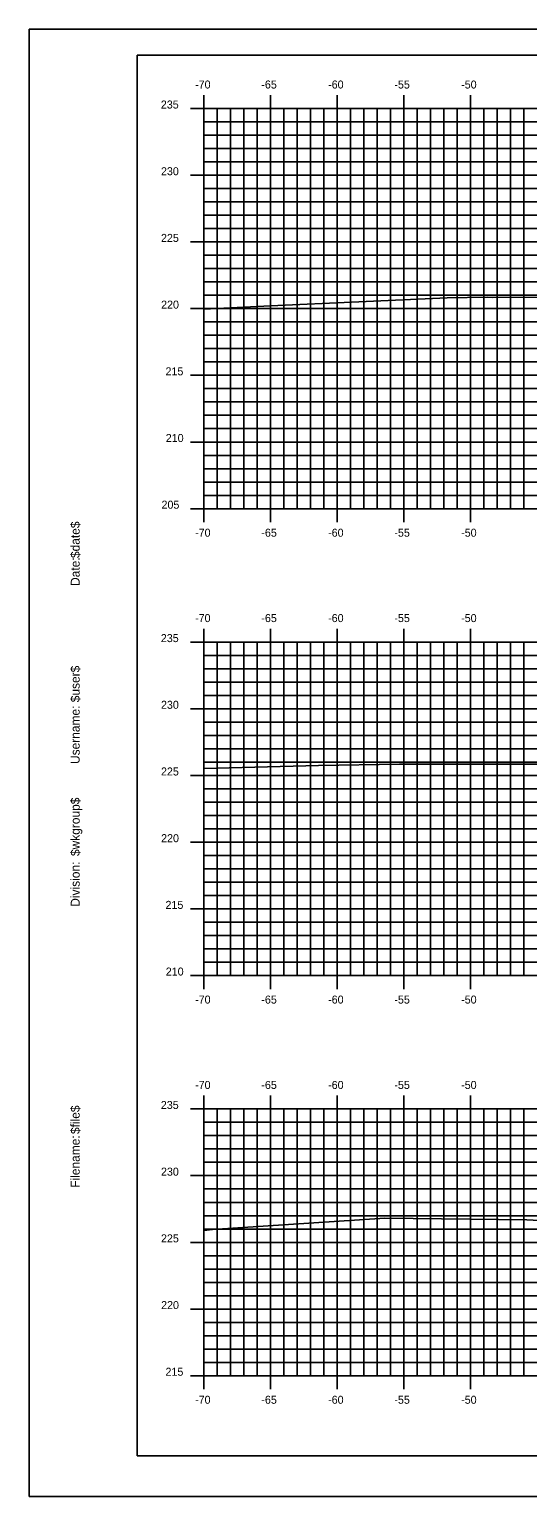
# Model space of a CAD drawing. Extents: x 1137876 to 1138046, y 608981 to 609091.
# Drawn here: x 1137876.1 to 1137913.5, y 608981.3 to 609091.3 of the extents above; entities that cross this region are included whole.
import ezdxf

# ---------------------------------------------------------------- set-up
doc = ezdxf.new("R2010")
doc.units = 0
for name, color, linetype in [('BORDER', 7, 'Continuous'), ('H_V ANNOTATION', 7, 'Continuous'), ('MAJOR', 7, 'Continuous'), ('MINOR', 7, 'Continuous'), ('PLOT BOUNDARY', 7, 'Continuous'), ('S_Roadway_Centerline', 7, 'Continuous')]:
    doc.layers.add(name, color=color, linetype=linetype)

msp = doc.modelspace()

# ---------------------------------------------------------------- linework, layer by layer
at = {"layer": 'BORDER'}
msp.add_lwpolyline([(1137884.17, 608984.34), (1138044.17, 608984.34), (1138044.17, 609089.34), (1137884.17, 609089.34)], close=True, dxfattribs=at)
at = {"layer": 'MAJOR'}
for p, q in [((1137889.17, 609086.34), (1137889.17, 609085.34)), ((1137894.17, 609086.34), (1137894.17, 609085.34)), ((1137899.17, 609086.34), (1137899.17, 609085.34)), ((1137904.17, 609086.34), (1137904.17, 609085.34)), ((1137909.17, 609086.34), (1137909.17, 609085.34)), ((1137888.16, 609085.34), (1137889.17, 609085.34)), ((1137889.17, 609085.34), (1138029.17, 609085.34)), ((1137889.17, 609055.34), (1137889.17, 609085.34)), ((1137889.17, 609055.34), (1137889.17, 609085.34)), ((1137889.17, 609085.34), (1138029.17, 609085.34)), ((1137894.17, 609055.34), (1137894.17, 609085.34)), ((1137899.17, 609055.34), (1137899.17, 609085.34)), ((1137904.17, 609055.34), (1137904.17, 609085.34)), ((1137909.17, 609055.34), (1137909.17, 609085.34)), ((1137888.16, 609080.34), (1137889.17, 609080.34)), ((1137889.17, 609080.34), (1138029.17, 609080.34)), ((1137888.16, 609075.34), (1137889.17, 609075.34)), ((1137889.17, 609075.34), (1138029.17, 609075.34)), ((1137888.16, 609070.34), (1137889.17, 609070.34)), ((1137889.17, 609070.34), (1138029.17, 609070.34)), ((1137888.16, 609065.34), (1137889.17, 609065.34)), ((1137889.17, 609065.34), (1138029.17, 609065.34)), ((1137888.16, 609060.34), (1137889.17, 609060.34)), ((1137889.17, 609060.34), (1138029.17, 609060.34)), ((1137888.16, 609055.34), (1137889.17, 609055.34)), ((1137889.17, 609055.34), (1138029.17, 609055.34)), ((1137889.17, 609055.34), (1138029.17, 609055.34)), ((1137889.17, 609054.33), (1137889.17, 609055.34)), ((1137894.17, 609054.33), (1137894.17, 609055.34)), ((1137899.17, 609054.33), (1137899.17, 609055.34)), ((1137904.17, 609054.33), (1137904.17, 609055.34)), ((1137909.17, 609054.33), (1137909.17, 609055.34)), ((1137889.17, 609046.34), (1137889.17, 609045.34)), ((1137894.17, 609046.34), (1137894.17, 609045.34)), ((1137899.17, 609046.34), (1137899.17, 609045.34)), ((1137904.17, 609046.34), (1137904.17, 609045.34)), ((1137909.17, 609046.34), (1137909.17, 609045.34)), ((1137888.16, 609045.34), (1137889.17, 609045.34)), ((1137889.17, 609045.34), (1138029.17, 609045.34)), ((1137889.17, 609020.34), (1137889.17, 609045.34)), ((1137889.17, 609020.34), (1137889.17, 609045.34)), ((1137889.17, 609045.34), (1138029.17, 609045.34)), ((1137894.17, 609020.34), (1137894.17, 609045.34)), ((1137899.17, 609020.34), (1137899.17, 609045.34)), ((1137904.17, 609020.34), (1137904.17, 609045.34)), ((1137909.17, 609020.34), (1137909.17, 609045.34)), ((1137888.16, 609040.34), (1137889.17, 609040.34)), ((1137889.17, 609040.34), (1138029.17, 609040.34)), ((1137888.16, 609035.34), (1137889.17, 609035.34)), ((1137889.17, 609035.34), (1138029.17, 609035.34)), ((1137888.16, 609030.34), (1137889.17, 609030.34)), ((1137889.17, 609030.34), (1138029.17, 609030.34)), ((1137888.16, 609025.34), (1137889.17, 609025.34)), ((1137889.17, 609025.34), (1138029.17, 609025.34)), ((1137888.16, 609020.34), (1137889.17, 609020.34)), ((1137889.17, 609020.34), (1138029.17, 609020.34)), ((1137889.17, 609020.34), (1138029.17, 609020.34)), ((1137889.17, 609019.33), (1137889.17, 609020.34)), ((1137894.17, 609019.33), (1137894.17, 609020.34)), ((1137899.17, 609019.33), (1137899.17, 609020.34)), ((1137904.17, 609019.33), (1137904.17, 609020.34)), ((1137909.17, 609019.33), (1137909.17, 609020.34)), ((1137889.17, 609011.34), (1137889.17, 609010.34)), ((1137894.17, 609011.34), (1137894.17, 609010.34)), ((1137899.17, 609011.34), (1137899.17, 609010.34)), ((1137904.17, 609011.34), (1137904.17, 609010.34)), ((1137909.17, 609011.34), (1137909.17, 609010.34)), ((1137888.16, 609010.34), (1137889.17, 609010.34)), ((1137889.17, 609010.34), (1138029.17, 609010.34)), ((1137889.17, 608990.34), (1137889.17, 609010.34)), ((1137889.17, 608990.34), (1137889.17, 609010.34)), ((1137889.17, 609010.34), (1138029.17, 609010.34)), ((1137894.17, 608990.34), (1137894.17, 609010.34)), ((1137899.17, 608990.34), (1137899.17, 609010.34)), ((1137904.17, 608990.34), (1137904.17, 609010.34)), ((1137909.17, 608990.34), (1137909.17, 609010.34)), ((1137888.16, 609005.34), (1137889.17, 609005.34)), ((1137889.17, 609005.34), (1138029.17, 609005.34)), ((1137888.16, 609000.34), (1137889.17, 609000.34)), ((1137889.17, 609000.34), (1138029.17, 609000.34)), ((1137888.16, 608995.34), (1137889.17, 608995.34)), ((1137889.17, 608995.34), (1138029.17, 608995.34)), ((1137888.16, 608990.34), (1137889.17, 608990.34)), ((1137889.17, 608990.34), (1138029.17, 608990.34)), ((1137889.17, 608990.34), (1138029.17, 608990.34)), ((1137889.17, 608989.33), (1137889.17, 608990.34)), ((1137894.17, 608989.33), (1137894.17, 608990.34)), ((1137899.17, 608989.33), (1137899.17, 608990.34)), ((1137904.17, 608989.33), (1137904.17, 608990.34)), ((1137909.17, 608989.33), (1137909.17, 608990.34))]:
    msp.add_line(p, q, dxfattribs=at)
at = {"layer": 'MINOR'}
for p, q in [((1137889.17, 609084.34), (1138029.17, 609084.34)), ((1137889.17, 609084.34), (1137890.17, 609084.34)), ((1137890.17, 609055.34), (1137890.17, 609085.34)), ((1137891.17, 609055.34), (1137891.17, 609085.34)), ((1137892.17, 609055.34), (1137892.17, 609085.34)), ((1137893.17, 609055.34), (1137893.17, 609085.34)), ((1137895.17, 609055.34), (1137895.17, 609085.34)), ((1137896.17, 609055.34), (1137896.17, 609085.34)), ((1137897.17, 609055.34), (1137897.17, 609085.34)), ((1137898.17, 609055.34), (1137898.17, 609085.34)), ((1137900.17, 609055.34), (1137900.17, 609085.34)), ((1137901.17, 609055.34), (1137901.17, 609085.34)), ((1137902.17, 609055.34), (1137902.17, 609085.34)), ((1137903.17, 609055.34), (1137903.17, 609085.34)), ((1137905.17, 609055.34), (1137905.17, 609085.34)), ((1137906.17, 609055.34), (1137906.17, 609085.34)), ((1137907.17, 609055.34), (1137907.17, 609085.34)), ((1137908.17, 609055.34), (1137908.17, 609085.34)), ((1137910.17, 609055.34), (1137910.17, 609085.34)), ((1137911.17, 609055.34), (1137911.17, 609085.34)), ((1137912.17, 609055.34), (1137912.17, 609085.34)), ((1137913.17, 609055.34), (1137913.17, 609085.34)), ((1137889.17, 609083.34), (1138029.17, 609083.34)), ((1137889.17, 609083.34), (1137890.17, 609083.34)), ((1137889.17, 609082.34), (1138029.17, 609082.34)), ((1137889.17, 609082.34), (1137890.17, 609082.34)), ((1137889.17, 609081.34), (1138029.17, 609081.34)), ((1137889.17, 609081.34), (1137890.17, 609081.34)), ((1137889.17, 609079.34), (1138029.17, 609079.34)), ((1137889.17, 609079.34), (1137890.17, 609079.34)), ((1137889.17, 609078.34), (1138029.17, 609078.34)), ((1137889.17, 609078.34), (1137890.17, 609078.34)), ((1137889.17, 609077.34), (1138029.17, 609077.34)), ((1137889.17, 609077.34), (1137890.17, 609077.34)), ((1137889.17, 609076.34), (1138029.17, 609076.34)), ((1137889.17, 609076.34), (1137890.17, 609076.34)), ((1137889.17, 609074.34), (1138029.17, 609074.34)), ((1137889.17, 609074.34), (1137890.17, 609074.34)), ((1137889.17, 609073.34), (1138029.17, 609073.34)), ((1137889.17, 609073.34), (1137890.17, 609073.34)), ((1137889.17, 609072.34), (1138029.17, 609072.34)), ((1137889.17, 609072.34), (1137890.17, 609072.34)), ((1137889.17, 609071.34), (1138029.17, 609071.34)), ((1137889.17, 609071.34), (1137890.17, 609071.34)), ((1137889.17, 609069.34), (1138029.17, 609069.34)), ((1137889.17, 609069.34), (1137890.17, 609069.34)), ((1137889.17, 609068.34), (1138029.17, 609068.34)), ((1137889.17, 609068.34), (1137890.17, 609068.34)), ((1137889.17, 609067.34), (1138029.17, 609067.34)), ((1137889.17, 609067.34), (1137890.17, 609067.34)), ((1137889.17, 609066.34), (1138029.17, 609066.34)), ((1137889.17, 609066.34), (1137890.17, 609066.34)), ((1137889.17, 609064.34), (1138029.17, 609064.34)), ((1137889.17, 609064.34), (1137890.17, 609064.34)), ((1137889.17, 609063.34), (1138029.17, 609063.34)), ((1137889.17, 609063.34), (1137890.17, 609063.34)), ((1137889.17, 609062.34), (1138029.17, 609062.34)), ((1137889.17, 609062.34), (1137890.17, 609062.34)), ((1137889.17, 609061.34), (1138029.17, 609061.34)), ((1137889.17, 609061.34), (1137890.17, 609061.34)), ((1137889.17, 609059.34), (1138029.17, 609059.34)), ((1137889.17, 609059.34), (1137890.17, 609059.34)), ((1137889.17, 609058.34), (1138029.17, 609058.34)), ((1137889.17, 609058.34), (1137890.17, 609058.34)), ((1137889.17, 609057.34), (1138029.17, 609057.34)), ((1137889.17, 609057.34), (1137890.17, 609057.34)), ((1137889.17, 609056.34), (1138029.17, 609056.34)), ((1137889.17, 609056.34), (1137890.17, 609056.34)), ((1137890.17, 609020.34), (1137890.17, 609045.34)), ((1137891.17, 609020.34), (1137891.17, 609045.34)), ((1137892.17, 609020.34), (1137892.17, 609045.34)), ((1137893.17, 609020.34), (1137893.17, 609045.34)), ((1137895.17, 609020.34), (1137895.17, 609045.34)), ((1137896.17, 609020.34), (1137896.17, 609045.34)), ((1137897.17, 609020.34), (1137897.17, 609045.34)), ((1137898.17, 609020.34), (1137898.17, 609045.34)), ((1137900.17, 609020.34), (1137900.17, 609045.34)), ((1137901.17, 609020.34), (1137901.17, 609045.34)), ((1137902.17, 609020.34), (1137902.17, 609045.34)), ((1137903.17, 609020.34), (1137903.17, 609045.34)), ((1137905.17, 609020.34), (1137905.17, 609045.34)), ((1137906.17, 609020.34), (1137906.17, 609045.34)), ((1137907.17, 609020.34), (1137907.17, 609045.34)), ((1137908.17, 609020.34), (1137908.17, 609045.34)), ((1137910.17, 609020.34), (1137910.17, 609045.34)), ((1137911.17, 609020.34), (1137911.17, 609045.34)), ((1137912.17, 609020.34), (1137912.17, 609045.34)), ((1137913.17, 609020.34), (1137913.17, 609045.34)), ((1137889.17, 609044.34), (1138029.17, 609044.34)), ((1137889.17, 609044.34), (1137890.17, 609044.34)), ((1137889.17, 609043.34), (1138029.17, 609043.34)), ((1137889.17, 609043.34), (1137890.17, 609043.34)), ((1137889.17, 609042.34), (1138029.17, 609042.34)), ((1137889.17, 609042.34), (1137890.17, 609042.34)), ((1137889.17, 609041.34), (1138029.17, 609041.34)), ((1137889.17, 609041.34), (1137890.17, 609041.34)), ((1137889.17, 609039.34), (1138029.17, 609039.34)), ((1137889.17, 609039.34), (1137890.17, 609039.34)), ((1137889.17, 609038.34), (1138029.17, 609038.34)), ((1137889.17, 609038.34), (1137890.17, 609038.34)), ((1137889.17, 609037.34), (1138029.17, 609037.34)), ((1137889.17, 609037.34), (1137890.17, 609037.34)), ((1137889.17, 609036.34), (1138029.17, 609036.34)), ((1137889.17, 609036.34), (1137890.17, 609036.34)), ((1137889.17, 609034.34), (1138029.17, 609034.34)), ((1137889.17, 609034.34), (1137890.17, 609034.34)), ((1137889.17, 609033.34), (1138029.17, 609033.34)), ((1137889.17, 609033.34), (1137890.17, 609033.34)), ((1137889.17, 609032.34), (1138029.17, 609032.34)), ((1137889.17, 609032.34), (1137890.17, 609032.34)), ((1137889.17, 609031.34), (1138029.17, 609031.34)), ((1137889.17, 609031.34), (1137890.17, 609031.34)), ((1137889.17, 609029.34), (1138029.17, 609029.34)), ((1137889.17, 609029.34), (1137890.17, 609029.34)), ((1137889.17, 609028.34), (1138029.17, 609028.34)), ((1137889.17, 609028.34), (1137890.17, 609028.34)), ((1137889.17, 609027.34), (1138029.17, 609027.34)), ((1137889.17, 609027.34), (1137890.17, 609027.34)), ((1137889.17, 609026.34), (1138029.17, 609026.34)), ((1137889.17, 609026.34), (1137890.17, 609026.34)), ((1137889.17, 609024.34), (1138029.17, 609024.34)), ((1137889.17, 609024.34), (1137890.17, 609024.34)), ((1137889.17, 609023.34), (1138029.17, 609023.34)), ((1137889.17, 609023.34), (1137890.17, 609023.34)), ((1137889.17, 609022.34), (1138029.17, 609022.34)), ((1137889.17, 609022.34), (1137890.17, 609022.34)), ((1137889.17, 609021.34), (1138029.17, 609021.34)), ((1137889.17, 609021.34), (1137890.17, 609021.34)), ((1137890.17, 608990.34), (1137890.17, 609010.34)), ((1137891.17, 608990.34), (1137891.17, 609010.34)), ((1137892.17, 608990.34), (1137892.17, 609010.34)), ((1137893.17, 608990.34), (1137893.17, 609010.34)), ((1137895.17, 608990.34), (1137895.17, 609010.34)), ((1137896.17, 608990.34), (1137896.17, 609010.34)), ((1137897.17, 608990.34), (1137897.17, 609010.34)), ((1137898.17, 608990.34), (1137898.17, 609010.34)), ((1137900.17, 608990.34), (1137900.17, 609010.34)), ((1137901.17, 608990.34), (1137901.17, 609010.34)), ((1137902.17, 608990.34), (1137902.17, 609010.34)), ((1137903.17, 608990.34), (1137903.17, 609010.34)), ((1137905.17, 608990.34), (1137905.17, 609010.34)), ((1137906.17, 608990.34), (1137906.17, 609010.34)), ((1137907.17, 608990.34), (1137907.17, 609010.34)), ((1137908.17, 608990.34), (1137908.17, 609010.34)), ((1137910.17, 608990.34), (1137910.17, 609010.34)), ((1137911.17, 608990.34), (1137911.17, 609010.34)), ((1137912.17, 608990.34), (1137912.17, 609010.34)), ((1137913.17, 608990.34), (1137913.17, 609010.34)), ((1137889.17, 609009.34), (1138029.17, 609009.34)), ((1137889.17, 609009.34), (1137890.17, 609009.34)), ((1137889.17, 609008.34), (1138029.17, 609008.34)), ((1137889.17, 609008.34), (1137890.17, 609008.34)), ((1137889.17, 609007.34), (1138029.17, 609007.34)), ((1137889.17, 609007.34), (1137890.17, 609007.34)), ((1137889.17, 609006.34), (1138029.17, 609006.34)), ((1137889.17, 609006.34), (1137890.17, 609006.34)), ((1137889.17, 609004.34), (1138029.17, 609004.34)), ((1137889.17, 609004.34), (1137890.17, 609004.34)), ((1137889.17, 609003.34), (1138029.17, 609003.34)), ((1137889.17, 609003.34), (1137890.17, 609003.34)), ((1137889.17, 609002.34), (1138029.17, 609002.34)), ((1137889.17, 609002.34), (1137890.17, 609002.34)), ((1137889.17, 609001.34), (1138029.17, 609001.34)), ((1137889.17, 609001.34), (1137890.17, 609001.34)), ((1137889.17, 608999.34), (1138029.17, 608999.34)), ((1137889.17, 608999.34), (1137890.17, 608999.34)), ((1137889.17, 608998.34), (1138029.17, 608998.34)), ((1137889.17, 608998.34), (1137890.17, 608998.34)), ((1137889.17, 608997.34), (1138029.17, 608997.34)), ((1137889.17, 608997.34), (1137890.17, 608997.34)), ((1137889.17, 608996.34), (1138029.17, 608996.34)), ((1137889.17, 608996.34), (1137890.17, 608996.34)), ((1137889.17, 608994.34), (1138029.17, 608994.34)), ((1137889.17, 608994.34), (1137890.17, 608994.34)), ((1137889.17, 608993.34), (1138029.17, 608993.34)), ((1137889.17, 608993.34), (1137890.17, 608993.34)), ((1137889.17, 608992.34), (1138029.17, 608992.34)), ((1137889.17, 608992.34), (1137890.17, 608992.34)), ((1137889.17, 608991.34), (1138029.17, 608991.34)), ((1137889.17, 608991.34), (1137890.17, 608991.34))]:
    msp.add_line(p, q, dxfattribs=at)
at = {"layer": 'PLOT BOUNDARY'}
msp.add_lwpolyline([(1137876.07, 608981.28), (1138046.07, 608981.28), (1138046.07, 609091.28), (1137876.07, 609091.28)], close=True, dxfattribs=at)
at = {"layer": 'S_Roadway_Centerline'}
for points in [[(1137889.17, 609070.31), (1137894.16, 609070.54), (1137907.42, 609071.16), (1137910.44, 609071.19), (1137910.79, 609071.18), (1137926.38, 609071.25), (1137927.33, 609071.57), (1137942.19, 609075.26), (1137946.06, 609075.7), (1137947.75, 609075.86), (1137957.88, 609075.91), (1137959.36, 609075.96), (1137960.7, 609075.9), (1137970.58, 609075.69), (1137973.49, 609075.36), (1137973.72, 609075.32), (1137986.06, 609069.74), (1137991.28, 609067.38), (1137992.63, 609067.18), (1137998.24, 609065.77), (1138001.57, 609065.61), (1138013.79, 609064.77), (1138025.43, 609064.46), (1138029.17, 609064.26)], [(1137889.17, 609035.87), (1137897.77, 609036.1), (1137903.85, 609036.2), (1137922.36, 609036.19), (1137923.65, 609036.23), (1137923.93, 609036.24), (1137941.45, 609035.5), (1137942.4, 609035.53), (1137948.19, 609035.51), (1137948.75, 609035.58), (1137958.38, 609035.6), (1137959.89, 609035.61), (1137962.57, 609035.56), (1137971.22, 609035.46), (1137975.09, 609034.7), (1137976.2, 609034.67), (1137977.29, 609034.41), (1137981.28, 609033.07), (1137986.63, 609031.59), (1137994.17, 609030.32)], [(1137889.17, 609001.22), (1137889.81, 609001.3), (1137902.75, 609002.16), (1137913.4, 609002.03), (1137925.07, 609001.42)]]:
    msp.add_lwpolyline(points, dxfattribs=at)

# ---------------------------------------------------------------- texts
at = {"layer": 'BORDER'}
for s, p in [('$date$', (1137879.85, 609051.64)), ('Date:', (1137879.85, 609049.55)), ('$user$', (1137879.85, 609040.83)), ('Username:', (1137879.85, 609036.2)), ('$wkgroup$', (1137879.85, 609029.3)), ('Division:', (1137879.85, 609025.5)), ('$file$', (1137879.85, 609008.46)), ('Filename:', (1137879.85, 609004.43))]:
    msp.add_text(s, height=0.67, rotation=90, dxfattribs=at).set_placement(p)
at = {"layer": 'H_V ANNOTATION'}
for s, p in [('-70', (1137888.51, 609086.84)), ('-65', (1137893.48, 609086.84)), ('-60', (1137898.49, 609086.84)), ('-55', (1137903.46, 609086.84)), ('-50', (1137908.47, 609086.84)), ('235', (1137885.94, 609085.34)), ('230', (1137885.95, 609080.34)), ('225', (1137885.95, 609075.34)), ('220', (1137885.96, 609070.34)), ('215', (1137886.29, 609065.34)), ('210', (1137886.31, 609060.34)), ('205', (1137885.99, 609055.34)), ('-70', (1137888.51, 609053.24)), ('-65', (1137893.48, 609053.24)), ('-60', (1137898.49, 609053.24)), ('-55', (1137903.46, 609053.24)), ('-50', (1137908.47, 609053.24)), ('-70', (1137888.51, 609046.84)), ('-65', (1137893.48, 609046.84)), ('-60', (1137898.49, 609046.84)), ('-55', (1137903.46, 609046.84)), ('-50', (1137908.47, 609046.84)), ('235', (1137885.94, 609045.34)), ('230', (1137885.95, 609040.34)), ('225', (1137885.95, 609035.34)), ('220', (1137885.96, 609030.34)), ('215', (1137886.29, 609025.34)), ('210', (1137886.31, 609020.34)), ('-70', (1137888.51, 609018.24)), ('-65', (1137893.48, 609018.24)), ('-60', (1137898.49, 609018.24)), ('-55', (1137903.46, 609018.24)), ('-50', (1137908.47, 609018.24)), ('-70', (1137888.51, 609011.84)), ('-65', (1137893.48, 609011.84)), ('-60', (1137898.49, 609011.84)), ('-55', (1137903.46, 609011.84)), ('-50', (1137908.47, 609011.84)), ('235', (1137885.94, 609010.34)), ('230', (1137885.95, 609005.34)), ('225', (1137885.95, 609000.34)), ('220', (1137885.96, 608995.34)), ('215', (1137886.29, 608990.34)), ('-70', (1137888.51, 608988.24)), ('-65', (1137893.48, 608988.24)), ('-60', (1137898.49, 608988.24)), ('-55', (1137903.46, 608988.24)), ('-50', (1137908.47, 608988.24))]:
    msp.add_text(s, height=0.6, dxfattribs=at).set_placement(p)
at = {"layer": 'MAJOR'}
for p in [(1137889.16, 609055.34), (1137889.16, 609020.34), (1137889.16, 608990.34)]:
    msp.add_text('-', height=0.006, dxfattribs=at).set_placement(p)

doc.saveas('drawing.dxf')
